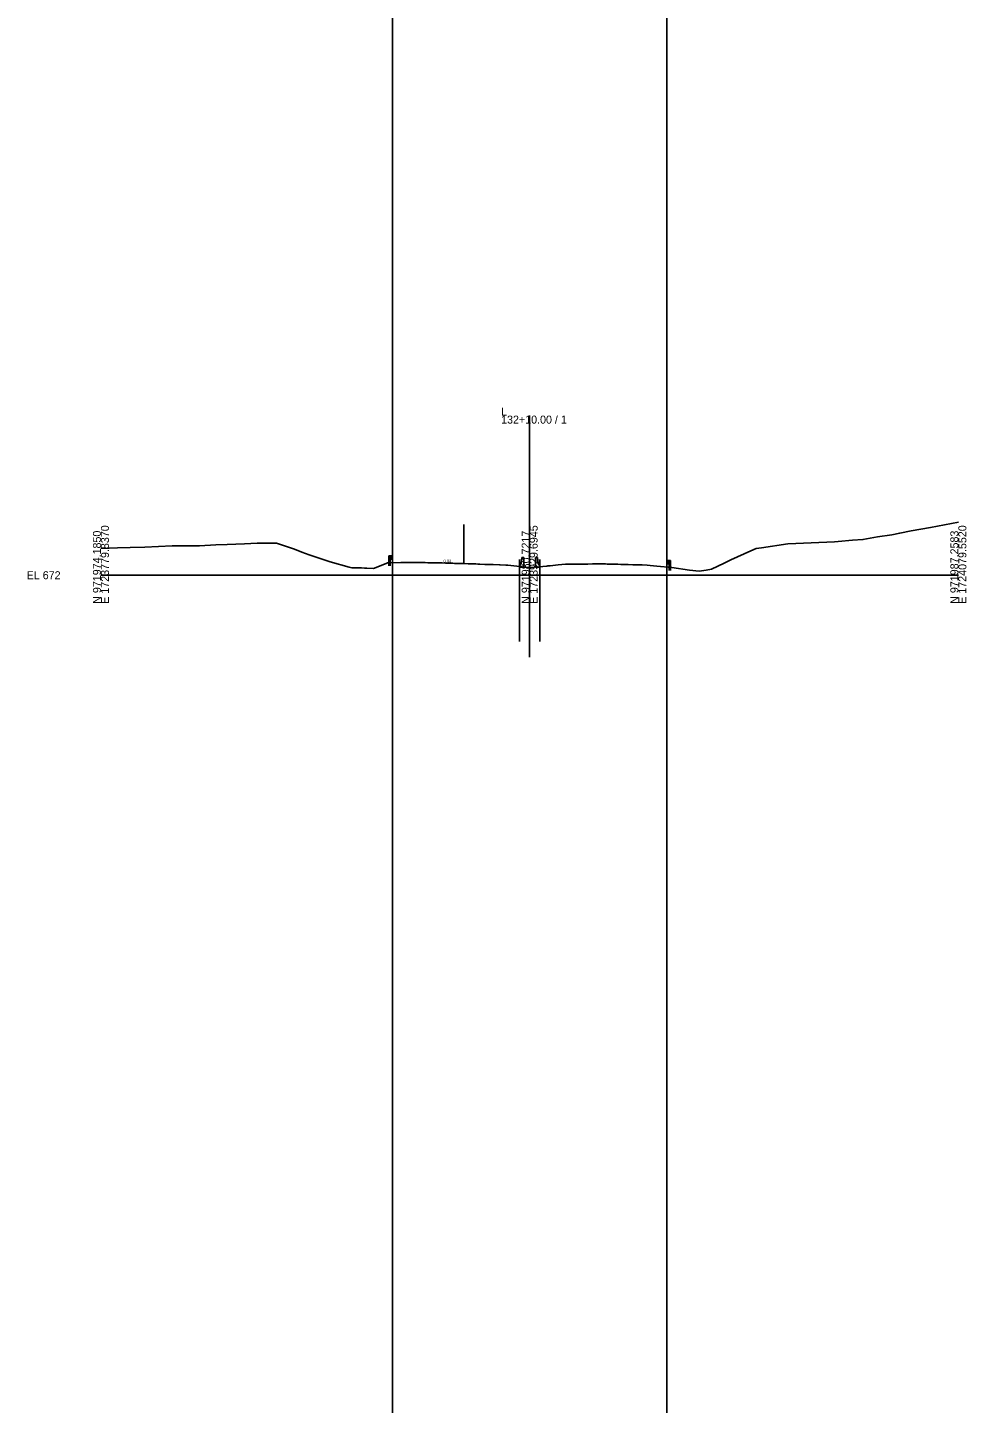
# Model space of a CAD drawing. Extents: x -26 to 303, y -29 to 15026.
# Drawn here: x -25.7 to 302.8, y 10210.1 to 10691.7 of the extents above; entities that cross this region are included whole.
import ezdxf

# ---------------------------------------------------------------- set-up
doc = ezdxf.new("R2010")
doc.units = 0
for name, color, linetype in [('Exist Cross Section Cell', 7, 'Continuous'), ('Exist XS Center Line Elevation Label', 7, 'Continuous'), ('Exist XS Ground Line', 7, 'Continuous'), ('Prop XS Ditch Standard Text', 7, 'Continuous'), ('Scratch_Level_0', 7, 'Continuous'), ('Typical Guardrail CELL', 7, 'Continuous'), ('Typical Median Barrier CELL', 7, 'Continuous')]:
    doc.layers.add(name, color=color, linetype=linetype)

msp = doc.modelspace()

# ---------------------------------------------------------------- linework, layer by layer
at = {"layer": 'Exist Cross Section Cell'}
for p, q in [((150, 10500), (150, 10555.87)), ((0, 10500), (150, 10500)), ((150, 10500), (300, 10500))]:
    msp.add_line(p, q, dxfattribs=at)
at = {"layer": 'Exist XS Ground Line'}
msp.add_lwpolyline([(0, 10509.33), (5.74, 10509.54), (10.19, 10509.71), (15.33, 10509.86), (20.19, 10510.09), (24.92, 10510.27), (30.2, 10510.24), (34.52, 10510.35), (40.21, 10510.59), (44.11, 10510.74), (50.22, 10510.99), (54.62, 10511.19), (61.45, 10511.26), (67.67, 10509.13), (70.24, 10508.04), (72.88, 10507.16), (80.25, 10504.73), (86.9, 10502.79), (87.33, 10502.66), (87.75, 10502.65), (91.22, 10502.59), (92.25, 10502.52), (93.06, 10502.5), (95.39, 10502.36), (99.79, 10504.08), (100.31, 10504.29), (101.15, 10504.32), (104.97, 10504.42), (107.6, 10504.48), (108.1, 10504.48), (109.39, 10504.48), (111.37, 10504.48), (111.89, 10504.46), (113.4, 10504.42), (114.39, 10504.39), (115.48, 10504.38), (116.89, 10504.36), (118.19, 10504.32), (119.38, 10504.29), (120.59, 10504.25), (121.87, 10504.22), (122.59, 10504.2), (123.09, 10504.18), (123.68, 10504.16), (124.36, 10504.14), (125.88, 10504.09), (126.86, 10504.07), (128.51, 10504.02), (129.36, 10504), (131.13, 10503.94), (131.85, 10503.91), (132.52, 10503.88), (134.37, 10503.81), (135.12, 10503.79), (135.69, 10503.77), (136.32, 10503.74), (136.86, 10503.72), (137.29, 10503.71), (139.4, 10503.64), (139.7, 10503.63), (141.65, 10503.56), (142.38, 10503.48), (145.51, 10503.15), (148.57, 10502.83), (150.26, 10502.67), (155.99, 10503.22), (156.41, 10503.28), (156.8, 10503.32), (157.14, 10503.35), (158.16, 10503.44), (159.96, 10503.62), (162.51, 10503.88), (162.98, 10503.89), (163.59, 10503.9), (164.2, 10503.91), (165.46, 10503.91), (166.93, 10503.91), (168.53, 10503.93), (169.42, 10503.93), (170.4, 10503.93), (171.94, 10503.94), (173.35, 10503.94), (174.44, 10503.95), (176.52, 10503.94), (177.07, 10503.93), (177.67, 10503.91), (179.42, 10503.86), (180.83, 10503.83), (181.91, 10503.81), (182.9, 10503.78), (184.42, 10503.74), (186.08, 10503.69), (186.92, 10503.67), (187.69, 10503.65), (189.33, 10503.6), (191.11, 10503.53), (192.18, 10503.46), (194.45, 10503.23), (199.69, 10502.66), (205.94, 10501.75), (209.29, 10501.39), (211.71, 10501.78), (213.62, 10502.11), (218.07, 10504.23), (220.37, 10505.37), (227.42, 10508.5), (229.24, 10509.35), (231.12, 10509.61), (240.39, 10511.01), (243.13, 10511.11), (248.54, 10511.35), (256.64, 10511.75), (257.99, 10511.78), (262.95, 10512.31), (266.58, 10512.5), (271.71, 10513.49), (276.67, 10514.17), (279.48, 10514.78), (283.47, 10515.53), (290.22, 10516.69), (300, 10518.62)], dxfattribs=at)
at = {"layer": 'Scratch_Level_0'}
for p, q in [((102, 15009.56), (102, -28.7)), ((198, 15009.56), (198, -28.7)), ((127, 10517.8), (127, 10504.06)), ((127, 10504.06), (116.89, 10504.36)), ((146.46, 10505.5), (146.46, 10476.8)), ((153.54, 10505.5), (153.54, 10476.8)), ((150, 10500), (150, 10471.3)), ((150, 10500), (150, 10471.3))]:
    msp.add_line(p, q, dxfattribs=at)
at = {"layer": 'Typical Guardrail CELL'}
for p, q in [((101.18, 10506.79), (100.68, 10506.79)), ((100.68, 10506.79), (100.68, 10504.3)), ((101.18, 10504.3), (100.68, 10504.3)), ((100.68, 10504.3), (100.68, 10503.3)), ((101.18, 10506.79), (101.18, 10504.3)), ((101.18, 10506.79), (101.68, 10506.79)), ((101.18, 10505.63), (101.68, 10505.63)), ((101.18, 10504.3), (101.18, 10503.3)), ((101.68, 10506.79), (101.68, 10505.63)), ((101.68, 10506.79), (101.97, 10506.59)), ((101.68, 10506.26), (101.97, 10506.46)), ((101.68, 10506.21), (101.68, 10506.26)), ((101.68, 10506.21), (101.68, 10506.16)), ((101.68, 10506.16), (101.97, 10505.96)), ((101.68, 10505.63), (101.97, 10505.83)), ((198.32, 10505.19), (198.03, 10504.99)), ((198.32, 10504.66), (198.03, 10504.86)), ((198.32, 10504.56), (198.03, 10504.36)), ((198.32, 10504.03), (198.03, 10504.23)), ((198.82, 10505.19), (198.32, 10505.19)), ((198.32, 10505.19), (198.32, 10504.03)), ((198.32, 10504.61), (198.32, 10504.66)), ((198.32, 10504.61), (198.32, 10504.56)), ((198.82, 10504.03), (198.32, 10504.03)), ((198.82, 10505.19), (198.82, 10502.7)), ((198.82, 10505.19), (199.32, 10505.19)), ((199.32, 10505.19), (199.32, 10502.7)), ((198.82, 10502.7), (199.32, 10502.7)), ((198.82, 10502.7), (198.82, 10501.7)), ((199.32, 10502.7), (199.32, 10501.7))]:
    msp.add_line(p, q, dxfattribs=at)
for centre, start, end in [((101.92, 10506.52), 304.9888, 54.997), ((101.92, 10505.9), 304.9634, 54.9941), ((198.08, 10504.92), 125.003, 235.0112), ((198.08, 10504.3), 125.0059, 235.0366)]:
    msp.add_arc(centre, 0.0776, start, end, dxfattribs=at)
at = {"layer": 'Typical Median Barrier CELL'}
for p, q in [((146.46, 10503.24), (146.92, 10503.9)), ((146.46, 10502.82), (146.46, 10503.24)), ((147.07, 10504.29), (147.29, 10506.24)), ((147.29, 10506.24), (147.96, 10506.24)), ((147.96, 10506.24), (147.96, 10502.82)), ((152.71, 10506.24), (152.04, 10506.24)), ((152.04, 10506.24), (152.04, 10502.82)), ((152.93, 10504.29), (152.71, 10506.24)), ((153.54, 10503.24), (153.08, 10503.9)), ((153.54, 10502.82), (153.54, 10503.24)), ((147.96, 10502.82), (146.46, 10502.82)), ((152.04, 10502.82), (153.54, 10502.82))]:
    msp.add_line(p, q, dxfattribs=at)
for centre, start, end in [((146.24, 10504.38), 325.0039, 353.9447), ((153.76, 10504.38), 186.0553, 214.9961)]:
    msp.add_arc(centre, 0.833, start, end, dxfattribs=at)

# ---------------------------------------------------------------- texts
at = {"layer": 'Exist Cross Section Cell'}
for s, p in [('132+10.00 / 1', (140, 10553.07)), ('L', (140, 10555.87)), ('EL 672', (-26, 10498.6))]:
    msp.add_text(s, height=2.8, dxfattribs=at).set_placement(p)
for s, p in [('E 1723779.8370', (2.8, 10490)), ('E 1724079.5520', (302.8, 10490)), ('N 971974.1850', (0, 10490)), ('N 971980.7217', (150, 10490)), ('E 1723929.6945', (152.8, 10490)), ('N 971987.2583', (300, 10490))]:
    msp.add_text(s, height=2.8, rotation=90, dxfattribs=at).set_placement(p)
at = {"layer": 'Exist XS Center Line Elevation Label'}
msp.add_text('674.69', height=0.18, dxfattribs=at).set_placement((149.62, 10502.2))
at = {"layer": 'Prop XS Ditch Standard Text'}
msp.add_text('0.03', height=1, rotation=358.325, dxfattribs=at).set_placement((119.85, 10504.51))

doc.saveas('drawing.dxf')
